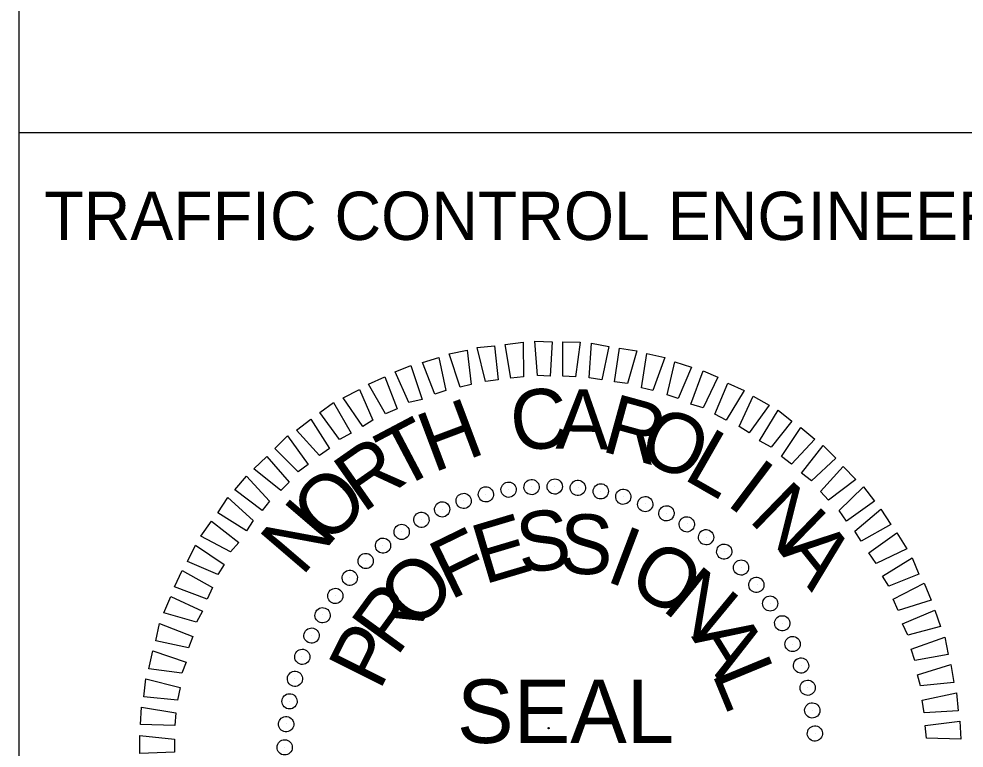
# Model space of a CAD drawing. Extents: x 1860868 to 1863318, y 1193312 to 1194425.
# Drawn here: x 1863048.9 to 1863138.2, y 1194218.6 to 1194287.4 of the extents above; entities that cross this region are included whole.
import ezdxf

# ---------------------------------------------------------------- set-up
doc = ezdxf.new("R2010")
doc.units = 0
for name, color, linetype in [('Prop Shade Light', 7, 'Continuous'), ('Sheet PE Seal CELL', 7, 'Continuous'), ('Sheet Plan CELL', 7, 'Continuous')]:
    doc.layers.add(name, color=color, linetype=linetype)

msp = doc.modelspace()

# ---------------------------------------------------------------- linework, layer by layer
at = {"layer": 'Prop Shade Light'}
for p, q in [((1863148.895, 1194276.658), (1863048.955, 1194276.658)), ((1863148.897, 1194276.658), (1863048.957, 1194276.658))]:
    msp.add_line(p, q, dxfattribs=at)
msp.add_circle((1863098.925, 1194220.437), 0.06, dxfattribs=at)
at = {"layer": 'Sheet PE Seal CELL'}
for p, q in [((1863095.163, 1194242.931), (1863095.163, 1194242.931)), ((1863097.313, 1194243.231), (1863097.313, 1194243.231)), ((1863099.513, 1194243.281), (1863099.513, 1194243.281)), ((1863101.713, 1194243.131), (1863101.713, 1194243.131)), ((1863090.863, 1194241.931), (1863090.863, 1194241.931)), ((1863092.963, 1194242.531), (1863092.963, 1194242.531)), ((1863103.863, 1194242.781), (1863103.863, 1194242.781)), ((1863105.963, 1194242.331), (1863105.963, 1194242.331)), ((1863088.863, 1194241.131), (1863088.863, 1194241.131)), ((1863108.063, 1194241.631), (1863108.063, 1194241.631)), ((1863086.913, 1194240.131), (1863086.913, 1194240.131)), ((1863110.063, 1194240.731), (1863110.063, 1194240.731)), ((1863112.013, 1194239.731), (1863112.013, 1194239.731)), ((1863085.013, 1194238.981), (1863085.013, 1194238.981)), ((1863113.813, 1194238.481), (1863113.813, 1194238.481)), ((1863083.263, 1194237.731), (1863083.263, 1194237.731)), ((1863115.563, 1194237.131), (1863115.563, 1194237.131)), ((1863081.613, 1194236.231), (1863081.613, 1194236.231)), ((1863117.113, 1194235.631), (1863117.113, 1194235.631)), ((1863080.113, 1194234.681), (1863080.113, 1194234.681)), ((1863118.613, 1194233.981), (1863118.613, 1194233.981)), ((1863078.763, 1194232.931), (1863078.763, 1194232.931)), ((1863119.863, 1194232.231), (1863119.863, 1194232.231)), ((1863077.513, 1194231.131), (1863077.513, 1194231.131)), ((1863121.013, 1194230.331), (1863121.013, 1194230.331)), ((1863076.513, 1194229.181), (1863076.513, 1194229.181)), ((1863122.013, 1194228.381), (1863122.013, 1194228.381)), ((1863075.613, 1194227.181), (1863075.613, 1194227.181)), ((1863122.813, 1194226.381), (1863122.813, 1194226.381)), ((1863074.913, 1194225.081), (1863074.913, 1194225.081)), ((1863123.413, 1194224.281), (1863123.413, 1194224.281)), ((1863074.463, 1194222.981), (1863074.463, 1194222.981)), ((1863123.813, 1194222.081), (1863123.813, 1194222.081)), ((1863074.113, 1194220.831), (1863074.113, 1194220.831)), ((1863124.113, 1194219.931), (1863124.113, 1194219.931)), ((1863073.963, 1194218.631), (1863073.963, 1194218.631))]:
    msp.add_line(p, q, dxfattribs=at)
for points in [[(1863092.963, 1194253.181), (1863092.163, 1194256.381), (1863093.813, 1194256.531), (1863094.163, 1194253.331)], [(1863095.363, 1194253.481), (1863094.813, 1194256.681), (1863096.513, 1194256.881), (1863096.563, 1194253.631)], [(1863097.863, 1194253.731), (1863097.613, 1194256.981), (1863099.263, 1194256.931), (1863099.063, 1194253.681)], [(1863100.263, 1194253.681), (1863100.263, 1194256.931), (1863101.913, 1194256.881), (1863101.463, 1194253.631)], [(1863102.763, 1194253.531), (1863102.963, 1194256.781), (1863104.613, 1194256.481), (1863103.963, 1194253.331)], [(1863105.163, 1194253.131), (1863105.613, 1194256.331), (1863107.263, 1194256.081), (1863106.363, 1194252.981)], [(1863088.163, 1194251.981), (1863087.013, 1194254.981), (1863088.563, 1194255.431), (1863089.213, 1194252.331)], [(1863090.563, 1194252.631), (1863089.513, 1194255.781), (1863091.213, 1194256.131), (1863091.613, 1194252.881)], [(1863107.713, 1194252.581), (1863108.213, 1194255.831), (1863109.913, 1194255.431), (1863108.763, 1194252.331)], [(1863085.713, 1194251.181), (1863084.413, 1194254.081), (1863085.913, 1194254.681), (1863086.963, 1194251.481)], [(1863110.113, 1194251.931), (1863110.863, 1194255.031), (1863112.413, 1194254.531), (1863111.163, 1194251.581)], [(1863083.513, 1194250.131), (1863081.913, 1194252.931), (1863083.463, 1194253.631), (1863084.613, 1194250.581)], [(1863112.363, 1194251.031), (1863113.513, 1194254.181), (1863114.913, 1194253.581), (1863113.513, 1194250.681)], [(1863114.613, 1194250.081), (1863115.863, 1194253.031), (1863117.413, 1194252.331), (1863115.713, 1194249.531)], [(1863081.363, 1194248.931), (1863079.513, 1194251.631), (1863081.063, 1194252.431), (1863082.313, 1194249.531)], [(1863116.913, 1194248.931), (1863118.263, 1194251.781), (1863119.763, 1194250.931), (1863117.863, 1194248.331)], [(1863079.163, 1194247.681), (1863077.313, 1194250.231), (1863078.613, 1194251.181), (1863080.263, 1194248.281)], [(1863118.863, 1194247.581), (1863120.613, 1194250.481), (1863121.913, 1194249.431), (1863119.963, 1194246.981)], [(1863077.263, 1194246.181), (1863075.113, 1194248.581), (1863076.463, 1194249.631), (1863078.213, 1194246.831)], [(1863120.913, 1194246.081), (1863122.763, 1194248.831), (1863124.063, 1194247.731), (1863121.863, 1194245.381)], [(1863075.263, 1194244.631), (1863073.063, 1194246.831), (1863074.263, 1194248.031), (1863076.213, 1194245.331)], [(1863122.813, 1194244.531), (1863124.863, 1194247.131), (1863126.063, 1194245.931), (1863123.763, 1194243.781)], [(1863073.613, 1194242.881), (1863071.063, 1194244.931), (1863072.313, 1194246.081), (1863074.413, 1194243.681)], [(1863124.613, 1194242.781), (1863126.763, 1194245.131), (1863127.963, 1194243.931), (1863125.363, 1194241.981)], [(1863071.863, 1194240.981), (1863069.263, 1194242.931), (1863070.363, 1194244.231), (1863072.563, 1194241.881)], [(1863126.363, 1194240.981), (1863128.663, 1194243.231), (1863129.713, 1194241.881), (1863127.063, 1194239.981)], [(1863070.363, 1194239.081), (1863067.663, 1194240.781), (1863068.613, 1194242.231), (1863071.013, 1194240.031)], [(1863127.863, 1194239.031), (1863130.313, 1194241.131), (1863131.263, 1194239.681), (1863128.463, 1194238.081)], [(1863068.863, 1194237.081), (1863066.063, 1194238.581), (1863067.063, 1194239.981), (1863069.663, 1194237.981)], [(1863129.163, 1194236.981), (1863131.813, 1194238.881), (1863132.763, 1194237.381), (1863129.863, 1194235.981)], [(1863067.663, 1194234.931), (1863064.813, 1194236.181), (1863065.563, 1194237.731), (1863068.263, 1194235.881)], [(1863130.463, 1194234.781), (1863133.263, 1194236.531), (1863133.913, 1194234.981), (1863131.063, 1194233.831)], [(1863066.663, 1194232.631), (1863063.563, 1194233.781), (1863064.313, 1194235.331), (1863067.163, 1194233.731)], [(1863131.463, 1194232.631), (1863134.413, 1194234.131), (1863135.063, 1194232.531), (1863131.963, 1194231.531)], [(1863065.663, 1194230.431), (1863062.563, 1194231.331), (1863063.213, 1194232.881), (1863066.213, 1194231.481)], [(1863132.363, 1194230.281), (1863135.413, 1194231.581), (1863135.963, 1194230.031), (1863132.863, 1194229.231)], [(1863064.913, 1194228.031), (1863061.813, 1194228.681), (1863062.163, 1194230.331), (1863065.313, 1194229.081)], [(1863133.163, 1194227.881), (1863136.363, 1194229.031), (1863136.663, 1194227.381), (1863133.513, 1194226.831)], [(1863064.263, 1194225.631), (1863061.163, 1194226.031), (1863061.513, 1194227.731), (1863064.663, 1194226.681)], [(1863133.763, 1194225.481), (1863136.913, 1194226.431), (1863137.213, 1194224.731), (1863134.063, 1194224.431)], [(1863063.863, 1194223.081), (1863060.663, 1194223.381), (1863060.863, 1194225.081), (1863064.113, 1194224.281)], [(1863134.213, 1194223.081), (1863137.463, 1194223.781), (1863137.613, 1194222.081), (1863134.413, 1194221.881)], [(1863063.613, 1194220.681), (1863060.363, 1194220.781), (1863060.463, 1194222.431), (1863063.713, 1194221.881)], [(1863134.513, 1194220.681), (1863137.763, 1194221.081), (1863137.863, 1194219.381), (1863134.613, 1194219.481)], [(1863063.563, 1194218.181), (1863060.313, 1194218.031), (1863060.313, 1194219.731), (1863063.563, 1194219.381)]]:
    msp.add_lwpolyline(points, close=True, dxfattribs=at)
for centre, major_axis in [((1863095.14, 1194242.952), (-0.113, 0.711)), ((1863097.313, 1194243.2), (-0.05, 0.718)), ((1863099.501, 1194243.257), (0.013, 0.72)), ((1863101.685, 1194243.124), (0.075, 0.716)), ((1863092.996, 1194242.516), (-0.174, 0.699)), ((1863103.848, 1194242.8), (0.137, 0.707)), ((1863105.976, 1194242.29), (0.198, 0.692)), ((1863088.862, 1194241.093), (-0.293, 0.658)), ((1863090.898, 1194241.895), (-0.234, 0.681)), ((1863108.051, 1194241.595), (0.258, 0.672)), ((1863110.057, 1194240.723), (0.316, 0.647)), ((1863086.904, 1194240.117), (-0.349, 0.63)), ((1863111.98, 1194239.679), (0.371, 0.617)), ((1863085.038, 1194238.973), (-0.403, 0.597)), ((1863113.805, 1194238.471), (0.423, 0.582)), ((1863083.28, 1194237.672), (-0.453, 0.56)), ((1863115.517, 1194237.109), (0.472, 0.543)), ((1863081.641, 1194236.222), (-0.5, 0.518)), ((1863117.104, 1194235.603), (0.518, 0.5)), ((1863080.135, 1194234.635), (-0.543, 0.472)), ((1863118.554, 1194233.965), (0.56, 0.453)), ((1863078.773, 1194232.923), (-0.582, 0.423)), ((1863119.855, 1194232.206), (0.597, 0.403)), ((1863077.565, 1194231.098), (-0.617, 0.371)), ((1863120.998, 1194230.34), (0.63, 0.349)), ((1863076.521, 1194229.176), (-0.647, 0.316)), ((1863121.975, 1194228.382), (0.658, 0.293)), ((1863075.649, 1194227.169), (-0.672, 0.258)), ((1863122.777, 1194226.346), (0.681, 0.234)), ((1863074.955, 1194225.094), (-0.692, 0.198)), ((1863123.398, 1194224.249), (0.699, 0.174)), ((1863074.444, 1194222.967), (-0.707, 0.137)), ((1863123.834, 1194222.105), (0.711, 0.113)), ((1863074.12, 1194220.803), (-0.716, 0.075)), ((1863124.082, 1194219.931), (0.718, 0.05)), ((1863073.987, 1194218.619), (-0.72, 0.013))]:
    msp.add_ellipse(centre, major_axis=major_axis, ratio=0.999708, dxfattribs=at)
at = {"layer": 'Sheet Plan CELL'}
msp.add_line((1863048.874, 1193362.487), (1863048.898, 1194387.485), dxfattribs=at)

# ---------------------------------------------------------------- texts
at = {"layer": 'Prop Shade Light'}
msp.add_text('TRAFFIC CONTROL ENGINEER', height=4.55726, rotation=0, dxfattribs=at).set_placement((1863051.274, 1194266.542))
at = {"layer": 'Sheet PE Seal CELL'}
for s, height, rotation, p in [('C', 5.638, 6.21987, (1863095.613, 1194246.531)), ('A', 5.638, 359.02032, (1863099.563, 1194246.831)), ('R', 5.638, 344.6211, (1863103.763, 1194246.631)), ('H', 5.638, 20.61948, (1863088.013, 1194244.531)), ('O', 5.638, 337.42116, (1863107.113, 1194245.881)), ('T', 5.638, 27.81977, (1863084.763, 1194242.881)), ('L', 5.638, 330.22088, (1863111.513, 1194244.031)), ('R', 5.639, 35.02051, (1863081.363, 1194240.681)), ('I', 5.638, 323.02014, (1863115.563, 1194241.631)), ('O', 5.638, 42.22174, (1863077.913, 1194237.581)), ('N', 5.639, 315.81891, (1863117.713, 1194240.081)), ('N', 5.639, 49.4235, (1863075.613, 1194234.681)), ('S', 5.638, 7.25561, (1863096.263, 1194235.031)), ('E', 5.638, 16.61107, (1863092.813, 1194233.981)), ('S', 5.638, 357.9004, (1863099.863, 1194235.081)), ('F', 5.638, 25.96703, (1863089.613, 1194232.481)), ('I', 5.638, 339.1896, (1863104.163, 1194234.381)), ('A', 5.639, 308.61715, (1863120.663, 1194237.131)), ('O', 5.638, 329.83348, (1863106.163, 1194233.681)), ('O', 5.639, 44.68124, (1863086.313, 1194229.531)), ('N', 5.638, 320.47661, (1863109.513, 1194231.681)), ('R', 5.639, 54.03965, (1863084.563, 1194227.081)), ('P', 5.639, 63.39889, (1863082.963, 1194223.881)), ('A', 5.639, 301.76027, (1863112.363, 1194229.081)), ('L', 5.639, 292.40085, (1863114.313, 1194225.631)), ('SEAL', 5.9982, 360, (1863090.264, 1194219.03))]:
    msp.add_text(s, height=height, rotation=rotation, dxfattribs=at).set_placement(p)

doc.saveas('drawing.dxf')
